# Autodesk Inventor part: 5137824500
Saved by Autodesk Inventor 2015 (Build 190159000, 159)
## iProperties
Created: 2020-07
Part Number: 5137824500
Checked By: TraceParts S.A.
Material: Generic
Catalog Web Link: www.traceparts.com
Document SubType Name: Modeling
Designer: TraceParts
Density: 1 g/cm^3
Appearance: Default
Company: TraceParts S.A.
Author: TraceParts
REFERENCE: 5137824500
DESIGN: CVAT/6-15000/710 N D PTC 1,5KW (230/400V) 50HZ - 5137824500
SUPPLIER: Soler & Palau
TraceParts.PartNumber: 10-14122018-105188
TraceParts.PartTitle: CVAT-N
TraceParts.InstanceId: 10-14122018-1051881PMR3DFNG0GI21HX661T0DNA9
TraceParts.PartStatus: Published
TraceParts.PartVersion: 1.0.4
TRACEPARTS: TRACEPARTS
TraceParts.PartLanguage: en
TraceParts.ClassPath: SOLER_PALAU:10-14122018-105188
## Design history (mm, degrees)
feature "5137824500"
body "Solid1"
